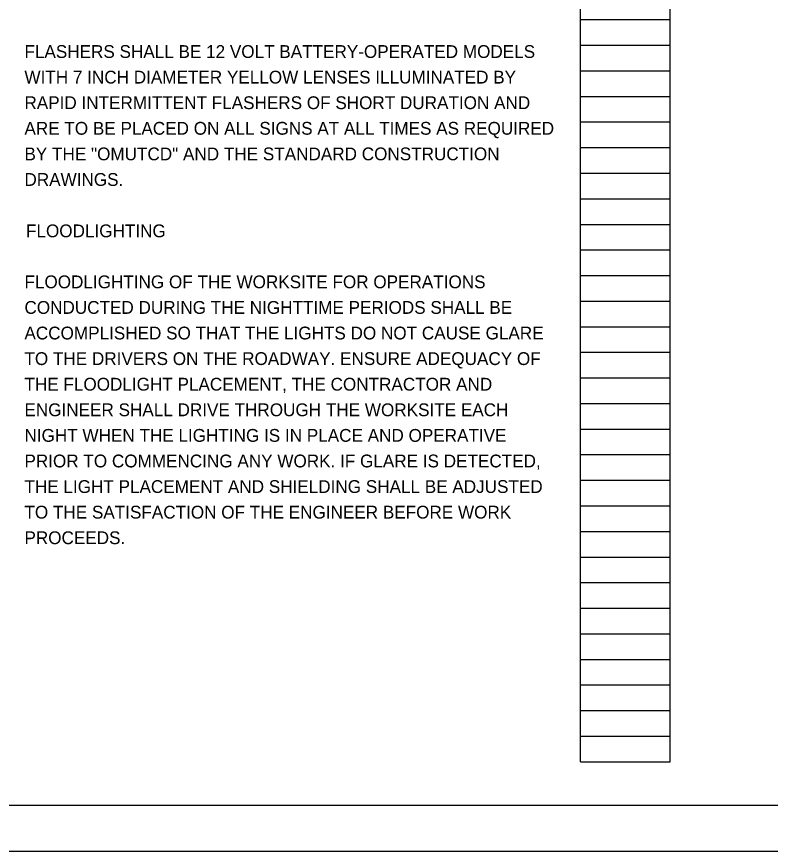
# Model space of a CAD drawing. Extents: x 0.1 to 34.1, y 0.2 to 22.2.
# Drawn here: x 17.62 to 25.86, y 0.17 to 9.3 of the extents above; entities that cross this region are included whole.
import ezdxf

# ---------------------------------------------------------------- set-up
doc = ezdxf.new("R2010")
doc.units = 0
for name, color, linetype in [('SH_Border', 7, 'Continuous'), ('SH_Cut_Line', 7, 'Continuous'), ('SH_Data', 7, 'Continuous'), ('SH_Text', 7, 'Continuous')]:
    doc.layers.add(name, color=color, linetype=linetype)

msp = doc.modelspace()

# ---------------------------------------------------------------- linework, layer by layer
at = {"layer": 'SH_Border'}
msp.add_lwpolyline([(1.6081, 21.6652), (33.6081, 21.6652), (33.6081, 0.6652), (1.6081, 0.6652)], close=True, dxfattribs=at)
at = {"layer": 'SH_Cut_Line'}
msp.add_lwpolyline([(0.1081, 0.1652), (34.1081, 0.1652), (34.1081, 22.1652), (0.1081, 22.1652)], close=True, dxfattribs=at)
at = {"layer": 'SH_Data'}
for p, q in [((23.7881, 1.1452), (23.7881, 21.3052)), ((24.7681, 1.1452), (24.7681, 21.3052)), ((23.7881, 9.2652), (24.7681, 9.2652)), ((23.7881, 8.9852), (24.7681, 8.9852)), ((23.7881, 8.7052), (24.7681, 8.7052)), ((23.7881, 8.4252), (24.7681, 8.4252)), ((23.7881, 8.1452), (24.7681, 8.1452)), ((23.7881, 7.8652), (24.7681, 7.8652)), ((23.7881, 7.5852), (24.7681, 7.5852)), ((23.7881, 7.3052), (24.7681, 7.3052)), ((23.7881, 7.0252), (24.7681, 7.0252)), ((23.7881, 6.7452), (24.7681, 6.7452)), ((23.7881, 6.4652), (24.7681, 6.4652)), ((23.7881, 6.1852), (24.7681, 6.1852)), ((23.7881, 5.9052), (24.7681, 5.9052)), ((23.7881, 5.6252), (24.7681, 5.6252)), ((23.7881, 5.3452), (24.7681, 5.3452)), ((23.7881, 5.0652), (24.7681, 5.0652)), ((23.7881, 4.7852), (24.7681, 4.7852)), ((23.7881, 4.5052), (24.7681, 4.5052)), ((23.7881, 4.2252), (24.7681, 4.2252)), ((23.7881, 3.9452), (24.7681, 3.9452)), ((23.7881, 3.6652), (24.7681, 3.6652)), ((23.7881, 3.3852), (24.7681, 3.3852)), ((23.7881, 3.1052), (24.7681, 3.1052)), ((23.7881, 2.8252), (24.7681, 2.8252)), ((23.7881, 2.5452), (24.7681, 2.5452)), ((23.7881, 2.2652), (24.7681, 2.2652)), ((23.7881, 1.9852), (24.7681, 1.9852)), ((23.7881, 1.7052), (24.7681, 1.7052)), ((23.7881, 1.4252), (24.7681, 1.4252)), ((23.7881, 1.1452), (24.7681, 1.1452))]:
    msp.add_line(p, q, dxfattribs=at)

# ---------------------------------------------------------------- texts
at = {"layer": 'SH_Text'}
for s, p in [('FLASHERS SHALL BE 12 VOLT BATTERY-OPERATED MODELS ', (17.7032, 8.846)), ('WITH 7 INCH DIAMETER YELLOW LENSES ILLUMINATED BY ', (17.7032, 8.566)), ('RAPID INTERMITTENT FLASHERS OF SHORT DURATION AND ', (17.7032, 8.286)), ('ARE TO BE PLACED ON ALL SIGNS AT ALL TIMES AS REQUIRED ', (17.7032, 8.006)), ('BY THE "OMUTCD" AND THE STANDARD CONSTRUCTION ', (17.7032, 7.726)), ('DRAWINGS.', (17.7032, 7.446)), ('FLOODLIGHTING', (17.7203, 6.884)), ('FLOODLIGHTING OF THE WORKSITE FOR OPERATIONS ', (17.7032, 6.326)), ('CONDUCTED DURING THE NIGHTTIME PERIODS SHALL BE ', (17.7032, 6.046)), ('ACCOMPLISHED SO THAT THE LIGHTS DO NOT CAUSE GLARE ', (17.7032, 5.766)), ('TO THE DRIVERS ON THE ROADWAY. ENSURE ADEQUACY OF ', (17.7032, 5.486)), ('THE FLOODLIGHT PLACEMENT, THE CONTRACTOR AND ', (17.7032, 5.206)), ('ENGINEER SHALL DRIVE THROUGH THE WORKSITE EACH ', (17.7032, 4.926)), ('NIGHT WHEN THE LIGHTING IS IN PLACE AND OPERATIVE ', (17.7032, 4.646)), ('PRIOR TO COMMENCING ANY WORK. IF GLARE IS DETECTED, ', (17.7032, 4.366)), ('THE LIGHT PLACEMENT AND SHIELDING SHALL BE ADJUSTED ', (17.7032, 4.086)), ('TO THE SATISFACTION OF THE ENGINEER BEFORE WORK ', (17.7032, 3.806)), ('PROCEEDS.', (17.7032, 3.526))]:
    msp.add_text(s, height=0.14, dxfattribs=at).set_placement(p)

doc.saveas('drawing.dxf')
